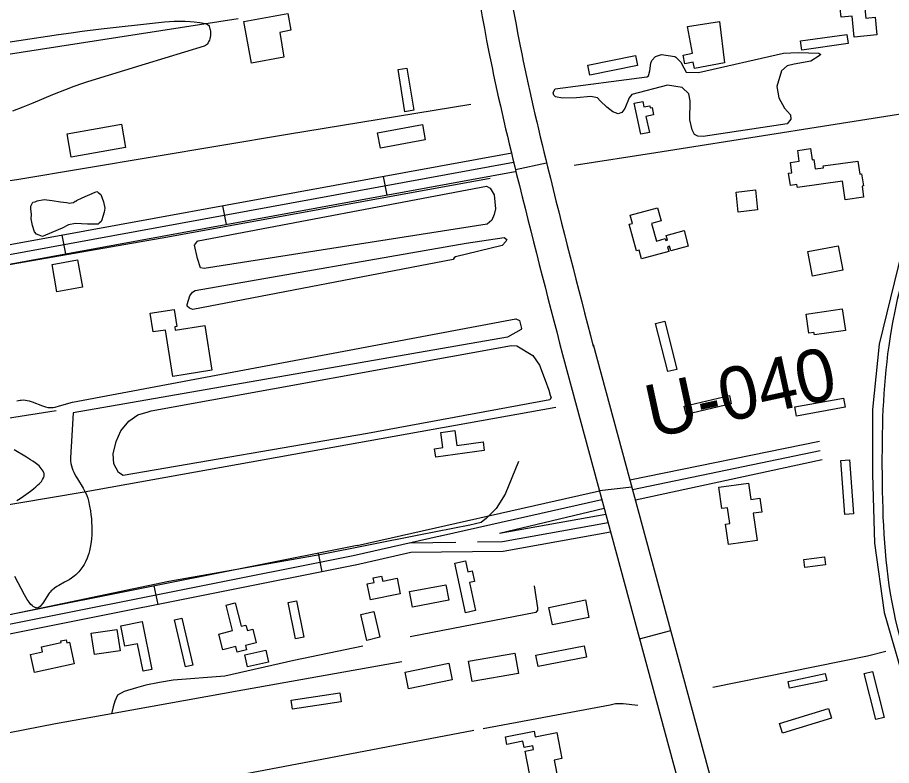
# Model space of a CAD drawing. Extents: x 3678539 to 3716648, y 451386 to 477139.
# Drawn here: x 3693361 to 3694736, y 458608 to 459785 of the extents above; entities that cross this region are included whole.
import ezdxf

# ---------------------------------------------------------------- set-up
doc = ezdxf.new("R2010")
doc.units = 0
for name, color, linetype in [('V-BLDG-OTLN', 7, 'Continuous'), ('V-RIVR-RANG-IDEN', 7, 'Continuous'), ('V-ROAD-CNTR', 7, 'Continuous'), ('V-SITE-VEGE', 7, 'Continuous'), ('V-TOPO-SHOR', 7, 'Continuous')]:
    doc.layers.add(name, color=color, linetype=linetype)

msp = doc.modelspace()

# ---------------------------------------------------------------- linework, layer by layer
at = {"layer": 'V-BLDG-OTLN'}
for points in [[(3694713.2, 459758), (3694677.3, 459754.6), (3694674.2, 459787.3), (3694657, 459785.7), (3694655.7, 459799.6), (3694652.3, 459799.2), (3694651, 459812.7), (3694658.8, 459813.5), (3694656.9, 459832.8), (3694682.6, 459835.2), (3694683.6, 459824.5), (3694691.9, 459825.3), (3694695.8, 459784.4), (3694710.5, 459785.8)], [(3693779.8, 459723.1), (3693729.1, 459713.7), (3693717, 459779), (3693786.2, 459791.8), (3693791.1, 459765.3), (3693773.6, 459761.6)], [(3694473.5, 459714.2), (3694426.2, 459705.2), (3694424.3, 459715.2), (3694410.8, 459712.6), (3694408.2, 459726.3), (3694423, 459729.1), (3694415, 459771.1), (3694465.6, 459778.9)], [(3694668.3, 459744.3), (3694594.9, 459733.9), (3694592.9, 459748.5), (3694666.2, 459758.9)], [(3694336.5, 459709.7), (3694261.6, 459694.7), (3694258.4, 459710.6), (3694333.3, 459725.7)], [(3693970.4, 459637.1), (3693959.7, 459703.4), (3693973.7, 459705.7), (3693984.3, 459639.3)], [(3694342, 459601.6), (3694331.4, 459650.5), (3694344.7, 459653.4), (3694346.6, 459644.5), (3694356, 459646.5), (3694356.7, 459643), (3694359.4, 459643.6), (3694361.8, 459632.2), (3694349.8, 459629.6), (3694355.2, 459604.5)], [(3693530.8, 459580.8), (3693445.2, 459565.7), (3693438.7, 459602.5), (3693524.2, 459617.6)], [(3694002.5, 459592.9), (3693931.9, 459579.5), (3693927.3, 459603.6), (3693997.9, 459617.1)], [(3694683.3, 459559.3), (3694686.2, 459538.8), (3694689.3, 459539.2), (3694692, 459520.4), (3694689.9, 459520.1), (3694692.4, 459502.4), (3694663.4, 459498.3), (3694659.2, 459527.9), (3694588.1, 459517.9), (3694587.5, 459522.4), (3694577.1, 459520.9), (3694574.3, 459540.3), (3694579.6, 459541), (3694577.3, 459557.2), (3694591.2, 459559.2), (3694588.8, 459576.2), (3694608.9, 459579.1), (3694611.4, 459561.5), (3694614.2, 459561.9), (3694616.3, 459546.9), (3694629.2, 459548.8), (3694628.8, 459551.6)], [(3694525.5, 459482.4), (3694495.1, 459479.1), (3694491.7, 459510.5), (3694522, 459513.9)], [(3694325.1, 459474), (3694368, 459485.8), (3694373.6, 459465.4), (3694358.6, 459461.3), (3694366.3, 459433.4), (3694380.2, 459437.2), (3694381, 459434.3), (3694383.5, 459435), (3694381.5, 459442.3), (3694409.8, 459450), (3694416.5, 459425.4), (3694389.1, 459417.9), (3694387.1, 459425.2), (3694383.8, 459424.2), (3694385.7, 459417.2), (3694342.8, 459405.5), (3694339.1, 459419.1), (3694334.9, 459417.9), (3694323.4, 459459.9), (3694328.5, 459461.3)], [(3694652.6, 459426), (3694659.9, 459387.4), (3694612, 459378.3), (3694604.7, 459416.9)], [(3693422.8, 459353.7), (3693415.1, 459396.5), (3693455.4, 459403.8), (3693463.1, 459361)], [(3693655.4, 459300.6), (3693666.5, 459229.9), (3693605, 459220.3), (3693593.5, 459293.3), (3693574.1, 459290.3), (3693569.5, 459320), (3693607.2, 459325.9), (3693611.5, 459298.9), (3693608.2, 459298.4), (3693609, 459293.3)], [(3694658.7, 459326.6), (3694663.7, 459292.7), (3694614.9, 459285.6), (3694614.3, 459289.4), (3694606.2, 459288.3), (3694601.8, 459318.3)], [(3694379.4, 459307.4), (3694398.5, 459231.4), (3694384.1, 459227.8), (3694365, 459303.8)], [(3694484.2, 459176.9), (3694412.9, 459160.3), (3694409.8, 459173.6), (3694481.1, 459190.2)], [(3694663.5, 459171.8), (3694587, 459157.8), (3694584.4, 459172.3), (3694660.8, 459186.2)], [(3694095.3, 459103.8), (3694019.1, 459093.1), (3694017.3, 459106.5), (3694030.2, 459108.3), (3694026.8, 459132.1), (3694048.8, 459135.2), (3694052.1, 459111.7), (3694093.4, 459117.5)], [(3694663, 459002.8), (3694656.5, 459088), (3694670.2, 459089.1), (3694676.7, 459003.9)], [(3694464.6, 459045.7), (3694511.1, 459052.4), (3694514.8, 459026.7), (3694529.1, 459028.7), (3694532.2, 459006.8), (3694518.8, 459004.9), (3694524.9, 458962.1), (3694479.6, 458955.6), (3694475, 458987.8), (3694481.7, 458988.7), (3694478.2, 459013.4), (3694469.3, 459012.2)], [(3694632.3, 458923.7), (3694600, 458919.5), (3694598.4, 458932.1), (3694630.7, 458936.2)], [(3694065.9, 458848.2), (3694049.3, 458926.3), (3694065.9, 458929.8), (3694069.5, 458912.8), (3694076.5, 458914.3), (3694080.1, 458897.3), (3694072.3, 458895.6), (3694081.7, 458851.5)], [(3693963.2, 458878.1), (3693916.5, 458868.4), (3693911.2, 458893.5), (3693921.9, 458895.7), (3693920.3, 458903.2), (3693933.8, 458906), (3693935.5, 458897.8), (3693958.1, 458902.5)], [(3693977.7, 458881.4), (3694035, 458892.4), (3694039.7, 458867.8), (3693982.4, 458856.9)], [(3693798.2, 458807.1), (3693786.8, 458864.4), (3693800, 458867), (3693811.4, 458809.7)], [(3694260.1, 458840.8), (3694202.8, 458829), (3694197.2, 458856.5), (3694254.5, 458868.3)], [(3693703.5, 458863.9), (3693712.8, 458827), (3693720.3, 458828.9), (3693722.5, 458820.4), (3693730.9, 458822.5), (3693736.3, 458801), (3693719.5, 458796.8), (3693721.3, 458789.7), (3693706.7, 458786), (3693704.4, 458795.2), (3693683.8, 458790), (3693677.6, 458814.7), (3693699.2, 458820.1), (3693689.1, 458860.2)], [(3693625.1, 458762.8), (3693607.8, 458836.9), (3693619.3, 458839.6), (3693636.7, 458765.5)], [(3693910.6, 458804.7), (3693900.9, 458845.5), (3693921.4, 458850.4), (3693931.1, 458809.6)], [(3693556.7, 458834.2), (3693572.1, 458758.9), (3693558.3, 458756), (3693549.4, 458799.4), (3693529.9, 458795.4), (3693523.4, 458827.4)], [(3693522.4, 458788.4), (3693482, 458782.3), (3693476.9, 458815.8), (3693517.3, 458822)], [(3693449.8, 458767.9), (3693387.4, 458754.1), (3693381.2, 458782.3), (3693400.1, 458786.5), (3693398.3, 458794.6), (3693429.7, 458801.5), (3693429.2, 458803.8), (3693437.5, 458805.6), (3693438.6, 458800.8), (3693442.4, 458801.7)], [(3693718.6, 458781.8), (3693751.5, 458789.1), (3693755.6, 458770.5), (3693722.7, 458763.2)], [(3694149.1, 458752.4), (3694076.1, 458740.1), (3694070.7, 458772.1), (3694143.7, 458784.4)], [(3694256.2, 458778.3), (3694180.1, 458763.6), (3694176.6, 458781.5), (3694252.8, 458796.2)], [(3694045, 458742.7), (3693976.3, 458728.5), (3693970.9, 458754.8), (3694039.6, 458769)], [(3694634.3, 458741.7), (3694576, 458729.5), (3694573.7, 458740.2), (3694632.1, 458752.4)], [(3694706.4, 458755.6), (3694724.7, 458683.5), (3694711.8, 458680.3), (3694693.5, 458752.4)], [(3693870.3, 458708.1), (3693793.8, 458696.3), (3693791.6, 458710.5), (3693868.1, 458722.3)], [(3694641.8, 458682.2), (3694564.6, 458658.4), (3694559.9, 458673.6), (3694637.1, 458697.4)], [(3694211.9, 458584.2), (3694170.3, 458576.1), (3694159.7, 458630.4), (3694172.8, 458633), (3694171.7, 458638.6), (3694158.3, 458635.9), (3694156.3, 458646), (3694131.1, 458641), (3694128.8, 458652.9), (3694173.7, 458661.7), (3694175.4, 458653), (3694209.4, 458659.7), (3694217.5, 458618.6), (3694205.6, 458616.3)]]:
    msp.add_lwpolyline(points, close=True, dxfattribs=at)
at = {"layer": 'V-ROAD-CNTR'}
for p, q in [((3693936.5, 459535.3), (3693941.9, 459505.8)), ((3693683.6, 459489.1), (3693689, 459459.6)), ((3693430.7, 459442.8), (3693436.1, 459413.3)), ((3693840.5, 458912.8), (3693834.7, 458942.2)), ((3693581.9, 458861.2), (3693576.1, 458890.6))]:
    msp.add_line(p, q, dxfattribs=at)
for points in [[(3694773.7, 460660.2), (3694807.1, 460551.7), (3694840.4, 460443.5), (3694869, 460342), (3694893.4, 460239.1), (3694905.8, 460152.7), (3694908.9, 460065.9), (3694906.4, 459994.5), (3694898.1, 459923.1), (3694879, 459821.7), (3694853.1, 459722.1), (3694825.2, 459641.2), (3694796.6, 459559.7), (3694752.8, 459417.2), (3694717, 459271), (3694706.4, 459168.3), (3694706.4, 459066.3), (3694709.7, 458957.9), (3694724.5, 458848.8), (3694763.1, 458716.5), (3694818.8, 458592.5), (3694899.5, 458442.4), (3694979.8, 458292.6)], [(3693127.3, 459387.4), (3694138.8, 459572.3)], [(3693130, 459372.6), (3694141.5, 459557.6)], [(3694144.4, 459546), (3694193.4, 459556.5)], [(3693132.7, 459357.8), (3694144.2, 459542.8)], [(3694266.9, 459270.4), (3694505, 458390.6), (3694642, 457876.7)], [(3694218.5, 459254.9), (3694218.5, 459254.9), (3694456.6, 458375.3), (3694593.5, 457861.5)], [(3694324.5, 459057.7), (3694622.9, 459118.6)], [(3694328.7, 459042.1), (3694624, 459103.7)], [(3694627.1, 459089.1), (3694333.2, 459025.5)], [(3694276.5, 459040.6), (3694327.5, 459046.7)], [(3693895.5, 458954.3), (3694276.7, 459040)], [(3694280.4, 459026.1), (3694026.6, 458968.8)], [(3694119.2, 458973.6), (3694283.9, 459013.1)], [(3694119.2, 458973.6), (3694286.6, 459003.3)], [(3694290.3, 458989.7), (3694123.9, 458959.7), (3694084.6, 458959.2)], [(3694025.8, 458968.6), (3693889.3, 458937.8)], [(3694294.2, 458975.2), (3694125.3, 458944.7), (3693979.9, 458942.9)], [(3693895.5, 458954.3), (3692334.7, 458643.1)], [(3694050.5, 458958.8), (3693978.2, 458957.9)], [(3693889.3, 458937.8), (3692337.6, 458628.4)], [(3693979.9, 458942.9), (3693892.6, 458923.2)], [(3693892.3, 458923.1), (3692340.5, 458613.7)], [(3694339.7, 458807.2), (3694388.8, 458820.1)]]:
    msp.add_lwpolyline(points, dxfattribs=at)
for points in [[(3694092.6, 461108.8), (3694067.8, 460806.3), (3694064.9, 460576.3), (3694077.1, 460310.3), (3694078.6, 460253.8), (3694103.2, 460036.9), (3694151.9, 459740.3), (3694195, 459550.1), (3694267, 459267.3)], [(3694032.5, 461094.4), (3694017.7, 460807.8), (3694014.8, 460575.4), (3694027, 460308.5), (3694028.6, 460250.3), (3694053.6, 460030.1), (3694102.7, 459730.7), (3694146.3, 459538.4), (3694218.5, 459254.9)], [(3694788, 460664.6), (3694854.8, 460447.7), (3694908.2, 460241.9), (3694923.9, 460065.9), (3694912.9, 459920.9), (3694867.4, 459717.8), (3694810.9, 459555), (3694731.9, 459268.4), (3694721.4, 459066.6), (3694739.2, 458851.9), (3694832.3, 458599.2), (3694993.1, 458299.7)]]:
    msp.add_spline(points, degree=3, dxfattribs=at)
at = {"layer": 'V-SITE-VEGE'}
for points in [[(3693237.7, 459730.2), (3693425.5, 459758.7), (3693445.1, 459761.5), (3693462.3, 459763.8), (3693492.4, 459767.5), (3693582.9, 459777.7), (3693592.1, 459778.7), (3693600.2, 459779.2), (3693607.3, 459779.6), (3693613.5, 459779.7), (3693624.4, 459779.5), (3693632.5, 459779), (3693638.6, 459778.5), (3693647.7, 459777.3), (3693656.8, 459775.7), (3693657.9, 459775.4), (3693658.8, 459775), (3693659.7, 459774.5), (3693661.1, 459773.1), (3693662.2, 459771.5), (3693663.1, 459769.7), (3693663.7, 459767.8), (3693664.1, 459765.9), (3693664.4, 459764), (3693664.6, 459760.4), (3693664.4, 459757.1), (3693663.9, 459754.2), (3693663.4, 459751.8), (3693662.7, 459749.7), (3693662.1, 459748), (3693660.7, 459745.3), (3693659.5, 459743.5), (3693658.4, 459742.4), (3693656.7, 459741.1), (3693655.8, 459740.6), (3693654.8, 459740.2), (3693561.9, 459712), (3693470.8, 459683.9), (3693463.3, 459681.4), (3693449.3, 459676.6), (3693437.2, 459672), (3693416.1, 459663.5), (3693384.7, 459650.4), (3693369, 459644), (3693353.1, 459638)], [(3693359.9, 459181.6), (3693365, 459182.9), (3693366.7, 459183.1), (3693370, 459183.3), (3693373.2, 459183.1), (3693376.1, 459182.6), (3693378.9, 459181.9), (3693384, 459180.3), (3693399.9, 459174), (3693404.9, 459172.4), (3693408.7, 459171.6), (3693411.5, 459171.2), (3693413.7, 459171.2), (3693416.8, 459171.4), (3693419.9, 459172), (3693426.8, 459174), (3693447.2, 459179.9), (3694145.3, 459311.1), (3694150.6, 459308.2), (3694154.2, 459295.7), (3694153.6, 459294), (3694131.8, 459282)], [(3694131.8, 459282), (3693448.5, 459162.7), (3693446.4, 459127.3), (3693444.3, 459092), (3693444.3, 459089.7), (3693444.4, 459087.5), (3693444.9, 459083.3), (3693445.7, 459079.5), (3693446.8, 459076), (3693448.1, 459072.7), (3693449.4, 459069.7), (3693452.3, 459064), (3693455.1, 459059.1), (3693464.1, 459044.2), (3693466.8, 459039.3), (3693468.6, 459035.6), (3693469.8, 459032.8), (3693471.4, 459028.6), (3693472.6, 459024.3), (3693474.3, 459016.1), (3693475.5, 459008.8), (3693476.4, 459002.3), (3693477, 458996.6), (3693477.4, 458991.6), (3693477.7, 458982.8), (3693477.7, 458976.3), (3693477.5, 458971.3), (3693477, 458964), (3693476.2, 458956.7), (3693475.1, 458950.8), (3693474, 458945.7), (3693472.8, 458941.3), (3693471.5, 458937.4), (3693470.3, 458934.1), (3693467.7, 458928.4), (3693465.5, 458924.2), (3693463.7, 458921.2), (3693460.6, 458916.7), (3693457.1, 458912.4), (3693454.8, 458909.9), (3693452.5, 458907.8), (3693450.2, 458905.9), (3693445.9, 458902.7), (3693441.9, 458900.2), (3693434.8, 458896.2), (3693425.7, 458891.2), (3693422.9, 458889.5), (3693418.9, 458886.9), (3693415.3, 458884), (3693413.7, 458882.5), (3693412.2, 458880.7), (3693410.8, 458878.9), (3693400.5, 458863.3), (3693398.1, 458860.2), (3693396.2, 458858.2), (3693394.8, 458857), (3693393.7, 458856.3), (3693392.9, 458855.9), (3693391.7, 458855.6), (3693390.5, 458855.7), (3693389.4, 458855.9), (3693387.3, 458856.8), (3693385.4, 458858.1), (3693383.6, 458859.7), (3693381.9, 458861.4), (3693378.9, 458865.1), (3693376.2, 458869), (3693373.9, 458872.8), (3693371.9, 458876.3), (3693356.7, 458905.4)], [(3693359.6, 459024.8), (3693364.9, 459028.1), (3693370.2, 459031.7), (3693381.2, 459039.7), (3693385.7, 459043.2), (3693389.4, 459046.2), (3693392.4, 459048.9), (3693394.9, 459051.2), (3693396.8, 459053.3), (3693398.3, 459055.1), (3693400.3, 459058), (3693401.6, 459060.4), (3693402.3, 459062.1), (3693402.6, 459063.4), (3693402.8, 459065.3), (3693402.6, 459067.2), (3693402.2, 459068.5), (3693401.2, 459071), (3693399.8, 459073.3), (3693398.2, 459075.5), (3693396.4, 459077.5), (3693394.6, 459079.3), (3693392.6, 459081), (3693388.7, 459084.2), (3693384.8, 459086.9), (3693381.3, 459089.2), (3693374.8, 459093.2), (3693355.3, 459104.7)]]:
    msp.add_lwpolyline(points, dxfattribs=at)
for points in [[(3694206.8, 459673.1), (3694351.1, 459691.8), (3694354, 459693.6), (3694355.8, 459701.3), (3694357.5, 459713.7), (3694359.2, 459717.9), (3694365.1, 459723.9), (3694374.5, 459726.9), (3694395.3, 459724.1), (3694397, 459722.9), (3694404.8, 459715.2), (3694409.6, 459706.4), (3694413.2, 459699.3), (3694432.7, 459698.9), (3694566.2, 459729.3), (3694589.3, 459730.1), (3694621.9, 459729.1), (3694624.8, 459727.3), (3694622.5, 459724.9), (3694609.5, 459716.6), (3694582.9, 459711.7), (3694572.3, 459709.2), (3694562.9, 459701.5), (3694555.9, 459676.6), (3694559, 459658.8), (3694568, 459642.9), (3694577.5, 459632.3), (3694577.6, 459625.2), (3694572.3, 459618.1), (3694439.9, 459598.3), (3694431.6, 459598.8), (3694426.2, 459601.2), (3694422.6, 459608.8), (3694419, 459624.2), (3694419.4, 459654.4), (3694417.5, 459665), (3694406.8, 459675), (3694383.7, 459679), (3694327.6, 459664.4), (3694323.5, 459659.1), (3694316.5, 459641.9), (3694311.8, 459635.9), (3694305.9, 459633.5), (3694297.6, 459637), (3694288.1, 459644.1), (3694278, 459654), (3694273.8, 459658.8), (3694263.1, 459661.1), (3694240.6, 459659.1), (3694218.7, 459658.4), (3694207.5, 459660.7), (3694205.1, 459663), (3694203.9, 459666.6), (3694204.5, 459668.4)], [(3693645, 459433.9), (3694098.9, 459519.7), (3694104.9, 459516.7), (3694110.8, 459506.1), (3694112.8, 459484.2), (3694111, 459475.4), (3694107.5, 459466.5), (3694099.9, 459459.9), (3693654.8, 459390.1), (3693648.8, 459391.3), (3693644, 459406), (3693639.1, 459426.7), (3693643.8, 459433.3)], [(3693640.2, 459355.7), (3694067, 459430.1), (3694126.7, 459438.8), (3694130.8, 459435.8), (3694129.1, 459432.9), (3694123.8, 459426.3), (3694049.9, 459408.7), (3694048.2, 459406.9), (3694046.4, 459404.5), (3693636.8, 459325.5), (3693631.5, 459327.8), (3693627.9, 459330.8), (3693627.9, 459333.7), (3693632, 459347.4), (3693636.1, 459352.7)], [(3693571, 459165.9), (3694138.4, 459269), (3694146.7, 459268.5), (3694171.7, 459253.3), (3694182.4, 459237.9), (3694191.4, 459214.3), (3694196.9, 459198.4), (3694199.3, 459190.7), (3694200.5, 459187.2), (3694198.7, 459183.6), (3693911.5, 459130.2), (3693527.3, 459064.4), (3693519.6, 459069.1), (3693512.4, 459082.7), (3693511.1, 459098.6), (3693516.3, 459117.6), (3693523.3, 459134.8), (3693536.2, 459149.7), (3693550.3, 459159.8), (3693566.3, 459164.7)]]:
    msp.add_lwpolyline(points, close=True, dxfattribs=at)
at = {"layer": 'V-TOPO-SHOR'}
for points in [[(3693708, 459783.2), (3693176.6, 459701.1), (3692819.7, 459642.3), (3692592.3, 459609.1), (3692333.3, 459563.6), (3692055.3, 459523.2), (3691970.7, 459504.2), (3691954.6, 459501.8)], [(3694074.1, 459648.4), (3693785.6, 459601.4), (3693359.6, 459530), (3693065.1, 459487.1), (3692813.5, 459446.8), (3692741.5, 459434)], [(3694797.1, 459640.6), (3694365.4, 459572.1), (3694237, 459552.3)], [(3694104.9, 459532), (3693597.2, 459439.3), (3693190.9, 459368.7), (3693091.3, 459350.5), (3692733.8, 459294.8), (3692315.9, 459225.3), (3692066.7, 459185), (3692040.1, 459182.5)], [(3693388.8, 459495), (3693391.7, 459496.8), (3693402.6, 459498.6), (3693415.3, 459497.5), (3693428.6, 459495.3), (3693437.8, 459494.2), (3693443, 459493.1), (3693445.3, 459493.7), (3693448.8, 459494.3), (3693451.6, 459496), (3693453.9, 459496.6), (3693453.4, 459497.2), (3693462.6, 459501.3), (3693483.2, 459510.6), (3693485.5, 459511.2), (3693486.7, 459510.7), (3693487.9, 459510.1), (3693491.9, 459506.7), (3693496, 459495.2), (3693498.4, 459485.4), (3693497.3, 459479), (3693495, 459472.1), (3693493.3, 459466.9), (3693492.2, 459464), (3693489.3, 459461.7), (3693487.6, 459459.9), (3693470.9, 459459.8), (3693451.9, 459460.9), (3693440.9, 459459.1), (3693431.2, 459453.8), (3693404.7, 459442.7), (3693400.1, 459440.4), (3693394.9, 459442.6), (3693390.9, 459444.3), (3693387.4, 459447.8), (3693384.5, 459458.1), (3693382.1, 459468.5), (3693382.6, 459475.4), (3693382, 459484), (3693382, 459488.1), (3693383.7, 459492.7), (3693384.8, 459494.4), (3693388.8, 459495)], [(3694207.8, 459171.4), (3693836.8, 459104.5), (3693465.8, 459038.2), (3693163.2, 458987), (3692843.7, 458931.6), (3692587.9, 458895.4), (3692169.9, 458849.9), (3692144.8, 458843.3), (3692136.1, 458841.6)], [(3693421.5, 459166.2), (3693104.9, 459116.3), (3692912, 459083.9), (3692706.5, 459050.3), (3692516, 459018), (3692476.9, 459013.1), (3692448.7, 459008.9), (3692340.5, 458989.7), (3692196.5, 458966.3), (3692125.7, 458954.9), (3692105.3, 458952.4)], [(3694149.1, 459086.5), (3694128.1, 459035.1), (3694113.9, 459012.5), (3694106.4, 459004.4), (3694099, 458996.9), (3694090.4, 458990.5), (3694072.6, 458986.3), (3693992.6, 458970.3), (3693836.6, 458939.3), (3693598.9, 458897.4), (3693290.5, 458832.6), (3693025.7, 458784.2), (3692715, 458721.6), (3692548.1, 458689.4), (3692295.4, 458639.4), (3692214.3, 458624.4), (3692199.9, 458622), (3692184.3, 458614.3)], [(3694174, 458890.6), (3694179.4, 458856.1), (3694179.4, 458852), (3694176.6, 458848.6), (3693978.6, 458810.4)], [(3693904.1, 458795.7), (3693795.4, 458773.1), (3693687.2, 458748.1), (3693605.6, 458742.3), (3693584.3, 458738.6), (3693562.5, 458734.3), (3693548.3, 458730.1), (3693528.8, 458724), (3693518.2, 458718.6), (3693514.1, 458709.1), (3693511.2, 458700.2), (3693508.6, 458689)], [(3694455, 458730.9), (3694698.5, 458780.4), (3694727.4, 458787.7)], [(3693965.6, 458771.1), (3693715.2, 458726.3), (3693508.6, 458689), (3693420.5, 458673.1), (3693082.1, 458606.9), (3692773.1, 458547.8), (3692531.4, 458503), (3692375.4, 458472.6), (3692234.7, 458443.1)], [(3694336.8, 458702.3), (3694313.8, 458705), (3694301.7, 458704.9), (3694293.6, 458702.6), (3694093.6, 458665.2)], [(3694079.1, 458663), (3693851, 458619), (3693579.4, 458567.7), (3693542, 458559.4), (3693513.8, 458554.6), (3693459.1, 458545), (3693282.4, 458509.3), (3693028.1, 458463.2), (3692674.1, 458397.6), (3692320.8, 458325), (3692276.5, 458321.1)]]:
    msp.add_lwpolyline(points, dxfattribs=at)

# ---------------------------------------------------------------- texts
at = {"layer": 'V-RIVR-RANG-IDEN'}
msp.add_text('U-040', height=83, rotation=12.2603, dxfattribs=at).set_placement((3694359.4, 459123))

doc.saveas('drawing.dxf')
